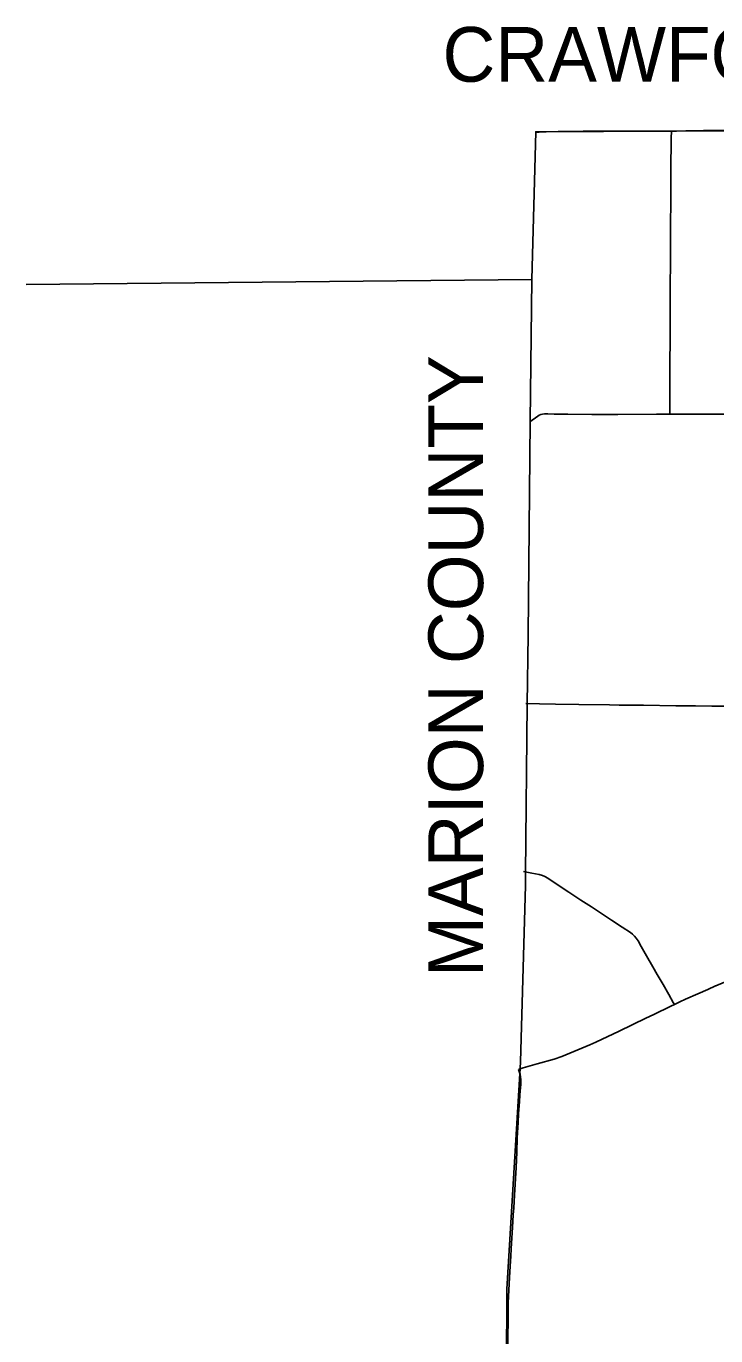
# Model space of a CAD drawing. Extents: x 1815539 to 1947826, y 273303 to 993194.
# Drawn here: x 1859869 to 1872474, y 966222 to 990160 of the extents above; entities that cross this region are included whole.
import ezdxf

# ---------------------------------------------------------------- set-up
doc = ezdxf.new("R2010")
doc.units = 0
for name, color, linetype in [('GM_X_Adjacent_County_Text', 7, 'Continuous'), ('GM_X_County', 7, 'Continuous'), ('GM_X_County_Road', 7, 'Continuous'), ('GM_X_State_Route', 7, 'Continuous'), ('GM_X_Township_Road', 7, 'Continuous'), ('PV_X_EOP', 7, 'Continuous')]:
    doc.layers.add(name, color=color, linetype=linetype)

msp = doc.modelspace()

# ---------------------------------------------------------------- linework, layer by layer
at = {"layer": 'GM_X_County'}
msp.add_lwpolyline([(1868643, 964155), (1868654, 967077), (1868896, 971111), (1868903, 971230), (1868993, 974454), (1868995, 974673), (1869028, 977767), (1869041, 979034), (1869083, 982941), (1869110, 985528), (1869183, 988230), (1871661, 988243), (1875677, 988261)], dxfattribs=at)
at = {"layer": 'GM_X_County_Road'}
for points in [[(1869191, 988216), (1869213, 988220), (1869245, 988225), (1869294, 988229), (1869376, 988231), (1869590, 988232), (1869803, 988236), (1870051, 988238), (1870416, 988241), (1870657, 988241), (1870838, 988241), (1871018, 988242), (1871297, 988242), (1871577, 988242), (1871661, 988242)], [(1871661, 988242), (1871757, 988241), (1871923, 988244), (1872250, 988251), (1872857, 988256), (1873350, 988258), (1873629, 988258), (1873925, 988259), (1874253, 988259), (1874417, 988258), (1874663, 988261), (1874844, 988260), (1875139, 988257), (1875402, 988259), (1875632, 988258), (1875672, 988258)], [(1869076, 982927), (1869218, 983033), (1869246, 983050), (1869276, 983063), (1869308, 983071), (1869340, 983074), (1869406, 983072), (1869520, 983067), (1869766, 983066), (1870209, 983065), (1870685, 983065), (1871390, 983066), (1871633, 983066)], [(1871633, 983066), (1871767, 983066), (1872276, 983066), (1872489, 983068), (1872915, 983067), (1872959, 983067)]]:
    msp.add_lwpolyline(points, dxfattribs=at)
at = {"layer": 'GM_X_State_Route'}
for points in [[(1871338, 972094), (1871654, 972249), (1871717, 972279), (1871817, 972327), (1871922, 972374), (1872146, 972475), (1872326, 972554), (1872469, 972616), (1872476, 972620), (1872631, 972687), (1872790, 972756), (1872807, 972764), (1873002, 972849), (1873123, 972901), (1873200, 972935), (1873363, 973008), (1873502, 973068), (1873573, 973099), (1873686, 973147), (1873708, 973156), (1873765, 973179), (1873807, 973197), (1873856, 973217)], [(1870169, 971540), (1870279, 971587), (1870709, 971792), (1871197, 972025), (1871338, 972094)], [(1868870, 971092), (1868952, 971118), (1869208, 971190), (1869518, 971281), (1869659, 971326), (1870169, 971540)]]:
    msp.add_lwpolyline(points, dxfattribs=at)
at = {"layer": 'GM_X_Township_Road'}
for points in [[(1871633, 983066), (1871633, 983101), (1871633, 983347), (1871636, 983986), (1871640, 984445), (1871642, 984658), (1871640, 984773), (1871638, 984953), (1871640, 985314), (1871643, 985937), (1871648, 986478), (1871650, 987003), (1871654, 987495), (1871660, 988135), (1871661, 988216), (1871661, 988242)], [(1869001, 977778), (1869250, 977773), (1869546, 977769), (1869972, 977762), (1870529, 977753), (1870709, 977751), (1871152, 977746), (1871743, 977739), (1872103, 977737), (1872399, 977733), (1872661, 977730), (1872775, 977729), (1872857, 977728), (1872883, 977728)], [(1871614, 972458), (1871510, 972641), (1871404, 972827), (1871321, 972968), (1871207, 973167), (1871110, 973339), (1871054, 973439), (1871018, 973492), (1870986, 973529), (1870951, 973563), (1870913, 973593), (1870763, 973693), (1870570, 973818), (1870364, 973953), (1870199, 974060), (1870007, 974186), (1869789, 974332), (1869611, 974449), (1869406, 974586), (1869350, 974618), (1869305, 974637), (1869243, 974653), (1869114, 974678), (1868957, 974709)], [(1871717, 972279), (1871697, 972314), (1871614, 972458)], [(1868668, 965744), (1868676, 966548), (1868681, 966827), (1868697, 967171), (1868710, 967400), (1868725, 967679), (1868732, 967810), (1868757, 968203), (1868771, 968432), (1868780, 968563), (1868794, 968792), (1868822, 969300), (1868834, 969579), (1868845, 969841), (1868860, 970120), (1868867, 970284), (1868883, 970496), (1868894, 970626), (1868908, 970823), (1868910, 970905), (1868906, 970955), (1868897, 971004), (1868888, 971037), (1868870, 971092)]]:
    msp.add_lwpolyline(points, dxfattribs=at)
at = {"layer": 'PV_X_EOP'}
msp.add_line((1869110, 985528), (1859869, 985436), dxfattribs=at)

# ---------------------------------------------------------------- texts
at = {"layer": 'GM_X_Adjacent_County_Text'}
msp.add_text('CRAWFORD COUNTY', height=1000, dxfattribs=at).set_placement((1867478, 989145))
msp.add_text('MARION COUNTY', height=1000, rotation=90, dxfattribs=at).set_placement((1868220, 972779))

doc.saveas('drawing.dxf')
